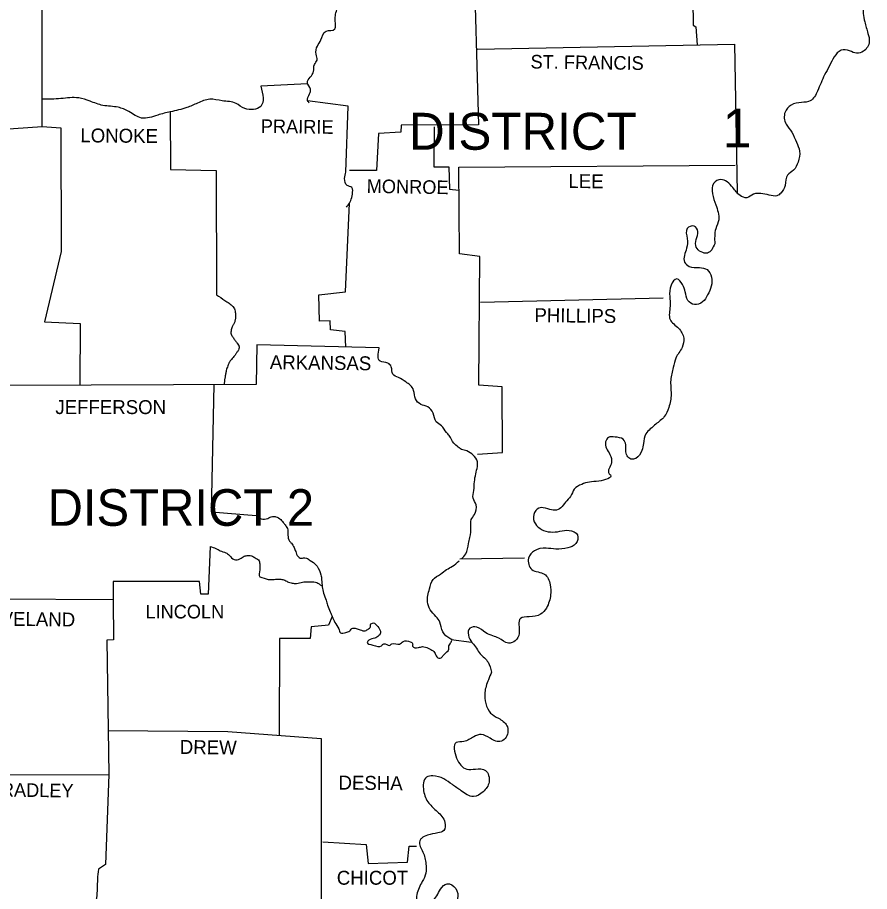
# Model space of a CAD drawing. Extents: x 1373884 to 1377798, y 1168424 to 1170626.
# Drawn here: x 1376598.2 to 1376861.3, y 1169816.4 to 1170086.2 of the extents above; entities that cross this region are included whole.
import ezdxf

# ---------------------------------------------------------------- set-up
doc = ezdxf.new("R2010")
doc.units = 0
doc.layers.add('R_Draft', color=7, linetype='Continuous')

msp = doc.modelspace()

# ---------------------------------------------------------------- linework, layer by layer
at = {"layer": 'R_Draft'}
for p, q in [((1376734.79, 1169919.1), (1376754.79, 1169919.4)), ((1376691.69, 1169911.1), (1376692.27, 1169910.78)), ((1376738.39, 1169893.3), (1376732.09, 1169894.1))]:
    msp.add_line(p, q, dxfattribs=at)
for points in [[(1376568.89, 1170039.7), (1376591.39, 1170039.8), (1376592.39, 1170051.6), (1376605.79, 1170052.6), (1376605.79, 1170106.2), (1376588.79, 1170106.7), (1376589.09, 1170159.4), (1376567.69, 1170160.8), (1376567.39, 1170184.4), (1376566.69, 1170185.6), (1376567.29, 1170200.4), (1376579.69, 1170200.8), (1376580.19, 1170213), (1376593.79, 1170213.5), (1376593.99, 1170221.4), (1376591.59, 1170224.5), (1376590.99, 1170231.2), (1376597.99, 1170232.2), (1376597.69, 1170257.1), (1376599.39, 1170257.2), (1376599.19, 1170281)], [(1376806.29, 1170122.79), (1376806.79, 1170083.9), (1376807.69, 1170083.3), (1376808.01, 1170077.77)], [(1376738.99, 1170107.9), (1376740.49, 1170053.1), (1376716.69, 1170053), (1376716.59, 1170050.8), (1376709.69, 1170050.4), (1376709.09, 1170039), (1376700.69, 1170039)], [(1376740.19, 1170076.4), (1376819.59, 1170078)], [(1376819.59, 1170078), (1376820.43, 1170032.2)], [(1376687.79, 1170065.7), (1376673.29, 1170065)], [(1376699.59, 1170038.5), (1376700.29, 1170058.9), (1376687.79, 1170060.5)], [(1376645.29, 1170057.08), (1376645.49, 1170039.3), (1376659.59, 1170039), (1376659.69, 1170000.6)], [(1376605.79, 1170052.6), (1376611.59, 1170052.2), (1376611.69, 1170014), (1376606.49, 1169992.3), (1376617.59, 1169991.8), (1376617.49, 1169972.69)], [(1376726.89, 1170052.5), (1376726.79, 1170040.1), (1376731.39, 1170040.1), (1376731.59, 1170033.2), (1376734.49, 1170032.9)], [(1376740.19, 1169951.4), (1376747.99, 1169951.9), (1376747.89, 1169972.2), (1376740.59, 1169972.7), (1376740.99, 1170012.4), (1376734.69, 1170013.3), (1376734.49, 1170040), (1376819.79, 1170040.6)], [(1376699.54, 1169984.48), (1376699.39, 1169989.3), (1376694.89, 1169989.8), (1376694.79, 1169992.6), (1376691.49, 1169992.5), (1376691.29, 1170000.6), (1376699.49, 1170001.5), (1376700.69, 1170028.9)], [(1376741.19, 1169998.3), (1376797.59, 1169999.7)], [(1376709.89, 1169984.2), (1376672.09, 1169985.2), (1376671.89, 1169972.9), (1376595.39, 1169972.6)], [(1376658.83, 1169972.85), (1376657.99, 1169933.6), (1376671.89, 1169932.5)], [(1376657.69, 1169922.9), (1376657.09, 1169908.2), (1376654.79, 1169908.2), (1376654.39, 1169912.1), (1376627.79, 1169912.1), (1376627.79, 1169906.5)], [(1376592.19, 1169906.8), (1376627.59, 1169906.6)], [(1376627.79, 1169906.6), (1376627.89, 1169894.1), (1376625.79, 1169894), (1376626.39, 1169852.5)], [(1376695.39, 1169901.3), (1376694.19, 1169898.6), (1376688.89, 1169898.1), (1376688.59, 1169894.5), (1376679.09, 1169894.5), (1376678.99, 1169864.6)], [(1376626.09, 1169866.1), (1376663.19, 1169865.8), (1376691.99, 1169863.6)], [(1376691.99, 1169863.6), (1376691.99, 1169803.8), (1376692.79, 1169746.3)], [(1376581.19, 1169852.4), (1376626.39, 1169852.5)], [(1376626.39, 1169852.5), (1376625.39, 1169824.7), (1376623.19, 1169823.3)], [(1376692.49, 1169831.7), (1376705.89, 1169830.9), (1376706.49, 1169825.1), (1376718.59, 1169825.5), (1376719.09, 1169830.4), (1376721.39, 1169830.4)]]:
    msp.add_lwpolyline(points, dxfattribs=at)
for points in [[(1376688.29, 1170059.8), (1376687.79, 1170060.5), (1376688.39, 1170062.7), (1376688.69, 1170064.1), (1376687.69, 1170066.1), (1376688.59, 1170067.8), (1376689.59, 1170069.6), (1376689.89, 1170071.7), (1376690.69, 1170073.1), (1376690.39, 1170074.9), (1376690.79, 1170077.4), (1376691.89, 1170079.3), (1376693.49, 1170082), (1376696.19, 1170082.7), (1376696.39, 1170083.8), (1376696.29, 1170086.3), (1376697.39, 1170090), (1376697.79, 1170091.3), (1376697.39, 1170092.5), (1376694.99, 1170093.9), (1376695.19, 1170096), (1376693.99, 1170098), (1376691.49, 1170098.9), (1376690.79, 1170102.3), (1376690.79, 1170105.3), (1376691.89, 1170108.2), (1376693.59, 1170110.3), (1376695.39, 1170111.1), (1376695.89, 1170113.1), (1376698.09, 1170115.3), (1376699.99, 1170116.2), (1376700.49, 1170119.5)], [(1376856.89, 1170115.5), (1376857.29, 1170112.6), (1376855.59, 1170109.5), (1376854.99, 1170106.4), (1376855.29, 1170103.3), (1376852.09, 1170101.6), (1376849.29, 1170099.6), (1376850.89, 1170097.2), (1376853.89, 1170095), (1376856.89, 1170093.3), (1376858.79, 1170091.6), (1376859.29, 1170087.5), (1376859.79, 1170084.9), (1376860.79, 1170081.3), (1376861.19, 1170078.8), (1376859.39, 1170075.8), (1376857.29, 1170075.2), (1376855.09, 1170075.9), (1376852.49, 1170076.1), (1376850.39, 1170074.1), (1376848.89, 1170071.3), (1376847.39, 1170068.5), (1376846.29, 1170066.1), (1376845.19, 1170063.5), (1376842.99, 1170060.5), (1376840.29, 1170060), (1376837.09, 1170059.2), (1376835.19, 1170057), (1376835.49, 1170053.3), (1376837.29, 1170050.8), (1376838.69, 1170047.7), (1376839.69, 1170045), (1376839.19, 1170041.6), (1376837.79, 1170039.1), (1376835.99, 1170037.6), (1376835.19, 1170034.4), (1376833.89, 1170032), (1376832.69, 1170031.2), (1376830.29, 1170031.4), (1376827.69, 1170031.9), (1376825.49, 1170031.7), (1376823.39, 1170030.6), (1376821.29, 1170031.3), (1376819.09, 1170033.7), (1376817.29, 1170035.5), (1376815.29, 1170036.2), (1376813.19, 1170035.1), (1376812.79, 1170031.8), (1376813.79, 1170028.4), (1376814.69, 1170023.8), (1376813.79, 1170021), (1376813.49, 1170016.4)], [(1376856.89, 1170115.5), (1376857.29, 1170112.6), (1376855.59, 1170109.5), (1376854.99, 1170106.4), (1376855.29, 1170103.3), (1376852.09, 1170101.6), (1376849.29, 1170099.6), (1376850.89, 1170097.2), (1376853.89, 1170095), (1376856.89, 1170093.3), (1376858.79, 1170091.6), (1376859.29, 1170087.5), (1376859.79, 1170084.9), (1376860.79, 1170081.3), (1376861.19, 1170078.8), (1376859.39, 1170075.8), (1376857.29, 1170075.2), (1376855.09, 1170075.9), (1376852.49, 1170076.1), (1376850.39, 1170074.1), (1376848.89, 1170071.3), (1376847.39, 1170068.5), (1376846.29, 1170066.1), (1376845.19, 1170063.5), (1376842.99, 1170060.5), (1376840.29, 1170060), (1376837.09, 1170059.2), (1376835.19, 1170057), (1376835.49, 1170053.3), (1376837.29, 1170050.8), (1376838.69, 1170047.7), (1376839.69, 1170045), (1376839.19, 1170041.6), (1376837.79, 1170039.1), (1376835.99, 1170037.6), (1376835.19, 1170034.4), (1376833.89, 1170032), (1376832.69, 1170031.2), (1376830.29, 1170031.4), (1376827.69, 1170031.9), (1376825.49, 1170031.7), (1376823.39, 1170030.6), (1376821.29, 1170031.3), (1376819.09, 1170033.7), (1376817.29, 1170035.5), (1376815.29, 1170036.2), (1376813.19, 1170035.1), (1376812.79, 1170031.8), (1376813.79, 1170028.4), (1376814.69, 1170023.8), (1376813.79, 1170021), (1376813.49, 1170016.4)], [(1376673.29, 1170065), (1376673.29, 1170058.8), (1376668.39, 1170058.1), (1376665.69, 1170059.7), (1376661.39, 1170060.5), (1376657.59, 1170061), (1376653.79, 1170059.8), (1376650.49, 1170058.4), (1376645.39, 1170057.1), (1376641.49, 1170056.1), (1376636.49, 1170055.2), (1376632.59, 1170057.2), (1376629.29, 1170058.5), (1376624.59, 1170059.1), (1376620.59, 1170060.4), (1376617.09, 1170061.4), (1376611.59, 1170061.2), (1376605.79, 1170060.99)], [(1376699.79, 1170027.7), (1376700.69, 1170028.9), (1376701.09, 1170029.7), (1376701.59, 1170031.7), (1376701.39, 1170033.7), (1376699.99, 1170034.4), (1376699.19, 1170036.5), (1376699.59, 1170038.5)], [(1376813.49, 1170016.4), (1376811.19, 1170013.5), (1376807.79, 1170015.3), (1376807.79, 1170017.7), (1376808.29, 1170020.2), (1376807.09, 1170021.8), (1376804.99, 1170021.1), (1376804.99, 1170018), (1376804.79, 1170015), (1376804.19, 1170010.7), (1376805.59, 1170009.4), (1376808.79, 1170009), (1376811.09, 1170008.4), (1376812.49, 1170006.1), (1376812.39, 1170003.3), (1376811.29, 1170000.6), (1376809.69, 1169998.4), (1376807.19, 1169997.6), (1376805.19, 1169998.9), (1376804.39, 1170001.5), (1376803.49, 1170003.8), (1376801.79, 1170005.5), (1376799.99, 1170003.6), (1376799.59, 1170000.1), (1376799.69, 1169997.1), (1376799.69, 1169993), (1376802.29, 1169990.3), (1376803.89, 1169987.2), (1376803.39, 1169984.4), (1376801.49, 1169981.1), (1376800.69, 1169978.2), (1376799.89, 1169974.3), (1376799.99, 1169970), (1376799.29, 1169965.8), (1376797.89, 1169963), (1376795.29, 1169960.7), (1376793.59, 1169959.2), (1376792.19, 1169957.7), (1376791.49, 1169954.7), (1376790.99, 1169952.6), (1376789.09, 1169950.1), (1376787.59, 1169949.9), (1376786.39, 1169950.9), (1376785.99, 1169952.6), (1376785.99, 1169954.3), (1376785.19, 1169956), (1376782.69, 1169956.7), (1376780.69, 1169956.6), (1376779.79, 1169955.2), (1376781.09, 1169951.3), (1376781.59, 1169948.8), (1376780.89, 1169945.4), (1376781.29, 1169945), (1376777.69, 1169943.1), (1376774.79, 1169942.8), (1376772.39, 1169942.1), (1376770.09, 1169940.6), (1376768.99, 1169938.4), (1376767.39, 1169936.6), (1376765.99, 1169934.9), (1376764.09, 1169934.1), (1376761.99, 1169934.5), (1376759.19, 1169934.8), (1376757.59, 1169932.8), (1376758.09, 1169929.9), (1376759.99, 1169928.2), (1376762.79, 1169927.4), (1376765.69, 1169927.6), (1376768.49, 1169927.9), (1376771.09, 1169926.5), (1376770.59, 1169923.8), (1376768.09, 1169922.5), (1376764.39, 1169922.1), (1376761.39, 1169922.4), (1376757.79, 1169921.6), (1376755.99, 1169919.3), (1376756.99, 1169915.8), (1376760.89, 1169914.4), (1376762.69, 1169911.1), (1376762.79, 1169908), (1376761.49, 1169903.9), (1376759.69, 1169902), (1376756.19, 1169901.2), (1376753.49, 1169900.7), (1376753.09, 1169896.1), (1376751.89, 1169893.8), (1376749.79, 1169893.1), (1376746.79, 1169894.6), (1376744.99, 1169895.3), (1376742.79, 1169896.3), (1376739.99, 1169898), (1376737.89, 1169897.7), (1376738.49, 1169893.3), (1376738.69, 1169893.1), (1376741.09, 1169889.8), (1376743.49, 1169887.2), (1376744.59, 1169884.1)], [(1376813.49, 1170016.4), (1376811.19, 1170013.5), (1376807.79, 1170015.3), (1376807.79, 1170017.7), (1376808.29, 1170020.2), (1376807.09, 1170021.8), (1376804.99, 1170021.1), (1376804.99, 1170018), (1376804.79, 1170015), (1376804.19, 1170010.7), (1376805.59, 1170009.4), (1376808.79, 1170009), (1376811.09, 1170008.4), (1376812.49, 1170006.1), (1376812.39, 1170003.3), (1376811.29, 1170000.6), (1376809.69, 1169998.4), (1376807.19, 1169997.6), (1376805.19, 1169998.9), (1376804.39, 1170001.5), (1376803.49, 1170003.8), (1376801.79, 1170005.5), (1376799.99, 1170003.6), (1376799.59, 1170000.1), (1376799.69, 1169997.1), (1376799.69, 1169993), (1376802.29, 1169990.3), (1376803.89, 1169987.2), (1376803.39, 1169984.4), (1376801.49, 1169981.1), (1376800.69, 1169978.2), (1376799.89, 1169974.3), (1376799.99, 1169970), (1376799.29, 1169965.8), (1376797.89, 1169963), (1376795.29, 1169960.7), (1376793.59, 1169959.2), (1376792.19, 1169957.7), (1376791.49, 1169954.7), (1376790.99, 1169952.6), (1376789.09, 1169950.1), (1376787.59, 1169949.9), (1376786.39, 1169950.9), (1376785.99, 1169952.6), (1376785.99, 1169954.3), (1376785.19, 1169956), (1376782.69, 1169956.7), (1376780.69, 1169956.6), (1376779.79, 1169955.2), (1376781.09, 1169951.3), (1376781.59, 1169948.8), (1376780.89, 1169945.4), (1376781.29, 1169945), (1376777.69, 1169943.1), (1376774.79, 1169942.8), (1376772.39, 1169942.1), (1376770.09, 1169940.6), (1376768.99, 1169938.4), (1376767.39, 1169936.6), (1376765.99, 1169934.9), (1376764.09, 1169934.1), (1376761.99, 1169934.5), (1376759.19, 1169934.8), (1376757.59, 1169932.8), (1376758.09, 1169929.9), (1376759.99, 1169928.2), (1376762.79, 1169927.4), (1376765.69, 1169927.6), (1376768.49, 1169927.9), (1376771.09, 1169926.5), (1376770.59, 1169923.8), (1376768.09, 1169922.5), (1376764.39, 1169922.1), (1376761.39, 1169922.4), (1376757.79, 1169921.6), (1376755.99, 1169919.3), (1376756.99, 1169915.8), (1376760.89, 1169914.4), (1376762.69, 1169911.1), (1376762.79, 1169908), (1376761.49, 1169903.9), (1376759.69, 1169902), (1376756.19, 1169901.2), (1376753.49, 1169900.7), (1376753.09, 1169896.1), (1376751.89, 1169893.8), (1376749.79, 1169893.1), (1376746.79, 1169894.6), (1376744.99, 1169895.3), (1376742.79, 1169896.3), (1376739.99, 1169898), (1376737.89, 1169897.7), (1376738.49, 1169893.3), (1376738.69, 1169893.1), (1376741.09, 1169889.8), (1376743.49, 1169887.2), (1376744.59, 1169884.1)], [(1376659.69, 1170000.6), (1376662.19, 1169998.9), (1376662.87, 1169998.46), (1376663.53, 1169998.01), (1376664.17, 1169997.52), (1376664.48, 1169997.23), (1376664.64, 1169997.07), (1376664.79, 1169996.9), (1376665.19, 1169996.28), (1376665.39, 1169995.6), (1376665.47, 1169994.9), (1376665.48, 1169994.55), (1376665.49, 1169994.2), (1376665.5, 1169993.73), (1376665.47, 1169993.25), (1376665.4, 1169992.77), (1376665.29, 1169992.3), (1376665.13, 1169991.89), (1376664.9, 1169991.49), (1376664.68, 1169991.11), (1376664.49, 1169990.7), (1376664.29, 1169990.08), (1376664.14, 1169989.43), (1376664.29, 1169988.2), (1376664.43, 1169987.97), (1376664.57, 1169987.74), (1376664.87, 1169987.29), (1376665.49, 1169986.4), (1376665.77, 1169986.03), (1376666.07, 1169985.65), (1376666.48, 1169985.09), (1376666.54, 1169985), (1376666.59, 1169984.9), (1376666.68, 1169984.26), (1376666.41, 1169983.57), (1376665.96, 1169982.87), (1376665.71, 1169982.53), (1376665.49, 1169982.2), (1376665.26, 1169981.87), (1376665.02, 1169981.56), (1376664.5, 1169980.97), (1376664.01, 1169980.37), (1376663.79, 1169980.04), (1376663.59, 1169979.7), (1376663.27, 1169979.02), (1376662.99, 1169978.33), (1376662.59, 1169976.9), (1376662.41, 1169975.89), (1376662.23, 1169974.89), (1376661.92, 1169972.86)], [(1376735.29, 1169919.1), (1376736.59, 1169920.7), (1376737.49, 1169923.8), (1376737.89, 1169925.7), (1376738.19, 1169929), (1376738.29, 1169931.2), (1376739.29, 1169932.8), (1376739.79, 1169935.8), (1376738.89, 1169937.8), (1376739.09, 1169940.2), (1376739.29, 1169942.9), (1376739.69, 1169945.3), (1376740.19, 1169947.6), (1376740.19, 1169949.1), (1376738.89, 1169951.1), (1376736.89, 1169952.4), (1376735.29, 1169952.9), (1376734.29, 1169953.6), (1376732.89, 1169954.8), (1376731.49, 1169957.2), (1376730.69, 1169958.1), (1376729.09, 1169960.2), (1376727.49, 1169961.4), (1376726.49, 1169964.1), (1376724.89, 1169966), (1376722.69, 1169966.8), (1376721.09, 1169968.5), (1376720.49, 1169971.1), (1376719.49, 1169972.7), (1376718.09, 1169973.7), (1376715.79, 1169975.1), (1376714.09, 1169976.1), (1376713.59, 1169978.4), (1376712.59, 1169979.5), (1376710.19, 1169980.1), (1376709.89, 1169984.2)], [(1376671.89, 1169932.5), (1376673.39, 1169931.5), (1376675.49, 1169931.6), (1376676.89, 1169932.2), (1376677.99, 1169932.1), (1376679.49, 1169931.2), (1376680.49, 1169930), (1376681.19, 1169929.1), (1376681.69, 1169927.7), (1376681.69, 1169926.4), (1376682.19, 1169924.6), (1376682.79, 1169923.9), (1376683.59, 1169922.6), (1376684.09, 1169921.4), (1376684.39, 1169920.6), (1376685.49, 1169919.3), (1376686.49, 1169919.4), (1376687.39, 1169919.3), (1376688.59, 1169918.6), (1376690.39, 1169917.2), (1376690.69, 1169916.8), (1376691.89, 1169914.2), (1376692.09, 1169912.6), (1376692.29, 1169910.5), (1376692.69, 1169908.5), (1376693.49, 1169906.3), (1376693.89, 1169904.8), (1376694.79, 1169902.7), (1376695.39, 1169901.3), (1376696.19, 1169899.5), (1376697.39, 1169897.5), (1376697.89, 1169896.3), (1376699.59, 1169896.4), (1376700.79, 1169896.9), (1376701.69, 1169897.7), (1376702.79, 1169897.6), (1376703.99, 1169897.2), (1376705.59, 1169896.9), (1376706.59, 1169897.5), (1376707.09, 1169897.9), (1376707.19, 1169898.8), (1376708.09, 1169899.3), (1376709.09, 1169898.6), (1376710.19, 1169897), (1376710.19, 1169896), (1376709.79, 1169895.4), (1376708.49, 1169894.6), (1376706.69, 1169894), (1376706.19, 1169893.3), (1376707.89, 1169892.5), (1376710.59, 1169892.3), (1376711.29, 1169892.9), (1376713.09, 1169892.4), (1376713.79, 1169892.9), (1376716.19, 1169892.8), (1376717.29, 1169893.6), (1376719.49, 1169893.5), (1376720.19, 1169893), (1376720.19, 1169892.1), (1376721.99, 1169891.7), (1376723.29, 1169892), (1376724.99, 1169891.5), (1376726.49, 1169890.7), (1376727.29, 1169889.6), (1376728.29, 1169888.4), (1376729.19, 1169888.7), (1376729.89, 1169889.6), (1376731.39, 1169891.2), (1376731.39, 1169892.2), (1376731.79, 1169892.9), (1376732.29, 1169893.9)], [(1376657.69, 1169922.9), (1376659.49, 1169922.3), (1376660.79, 1169921.6), (1376662.49, 1169921), (1376663.59, 1169920.2), (1376665.09, 1169918.9), (1376666.89, 1169919.1), (1376668.19, 1169919.9), (1376669.49, 1169920.1), (1376670.49, 1169920), (1376671.59, 1169919.4), (1376672.79, 1169918.5), (1376672.99, 1169917.2), (1376672.99, 1169915.7), (1376672.99, 1169913.6), (1376673.69, 1169913.3), (1376676.19, 1169912.7), (1376677.89, 1169912.8), (1376679.49, 1169912.8), (1376680.79, 1169912.5), (1376681.89, 1169911.9), (1376682.69, 1169911.7), (1376683.89, 1169911.5), (1376684.89, 1169911.6), (1376686.59, 1169912), (1376687.59, 1169912), (1376689.19, 1169912), (1376690.19, 1169911.9), (1376691.69, 1169911.1)], [(1376732.39, 1169894.2), (1376731.69, 1169894.5), (1376729.49, 1169896.6), (1376728.59, 1169899.6), (1376727.39, 1169901.3), (1376725.59, 1169903.4), (1376724.79, 1169905.8), (1376725.39, 1169909.8), (1376726.49, 1169912.7), (1376728.79, 1169914.4), (1376730.69, 1169915.8), (1376732.49, 1169916.8), (1376734.59, 1169918.5)], [(1376744.59, 1169884.1), (1376743.59, 1169881.8), (1376742.49, 1169877.8), (1376742.79, 1169874.4), (1376744.29, 1169871.5), (1376746.69, 1169869.9), (1376749.29, 1169867.6), (1376749.09, 1169864.1), (1376747.59, 1169862.8), (1376744.09, 1169863.7), (1376741.39, 1169864.9), (1376739.09, 1169864.2), (1376735.99, 1169862.7), (1376733.69, 1169862.4), (1376733.79, 1169857.6), (1376736.89, 1169854.2), (1376739.59, 1169854.2), (1376742.69, 1169853.8), (1376743.79, 1169850.2), (1376741.99, 1169847.2), (1376738.99, 1169845.7), (1376735.19, 1169847.5), (1376732.49, 1169849.4), (1376729.79, 1169851.2), (1376726.39, 1169852.1), (1376724.49, 1169851.7), (1376723.59, 1169847.5), (1376725.19, 1169843.7), (1376727.79, 1169841.1), (1376730.19, 1169837.7), (1376729.79, 1169835.2), (1376727.99, 1169834.5), (1376724.79, 1169833.8), (1376722.89, 1169832.8), (1376722.39, 1169832), (1376723.39, 1169828.6), (1376724.29, 1169824.9), (1376724.29, 1169822.1), (1376723.19, 1169819.5), (1376721.49, 1169815.5), (1376721.69, 1169812.9), (1376722.89, 1169811.7), (1376724.39, 1169812.1), (1376726.39, 1169813.5), (1376727.69, 1169815.1), (1376728.79, 1169817.1), (1376730.89, 1169818.8), (1376733.49, 1169817.3), (1376734.09, 1169814.2), (1376732.59, 1169811.5), (1376730.49, 1169810.3), (1376727.89, 1169809.3), (1376725.99, 1169807.1), (1376726.49, 1169804.5), (1376727.99, 1169803.1), (1376731.69, 1169803.8), (1376734.19, 1169804.9), (1376735.59, 1169806.3), (1376737.29, 1169808), (1376738.19, 1169809.7), (1376739.49, 1169811.5), (1376741.79, 1169812), (1376742.89, 1169810.5), (1376742.49, 1169807.1), (1376741.09, 1169803.9), (1376739.19, 1169801.2), (1376737.09, 1169799.3), (1376734.49, 1169795.2), (1376734.99, 1169791.4), (1376735.99, 1169788.3), (1376737.39, 1169785.9), (1376739.79, 1169786.4), (1376742.49, 1169786.7), (1376744.09, 1169785.4), (1376743.89, 1169782.6), (1376741.89, 1169779.9), (1376739.99, 1169777.3), (1376738.99, 1169773.7), (1376739.39, 1169771.2), (1376739.39, 1169768.9), (1376738.59, 1169766.4), (1376737.19, 1169765), (1376733.49, 1169765.1), (1376729.59, 1169765.5), (1376727.49, 1169764.3), (1376727.89, 1169760.9), (1376730.19, 1169758.4), (1376731.79, 1169757.1), (1376734.09, 1169754.3), (1376735.09, 1169752), (1376734.79, 1169750), (1376733.39, 1169748.3), (1376729.29, 1169746.3)], [(1376744.59, 1169884.1), (1376743.59, 1169881.8), (1376742.49, 1169877.8), (1376742.79, 1169874.4), (1376744.29, 1169871.5), (1376746.69, 1169869.9), (1376749.29, 1169867.6), (1376749.09, 1169864.1), (1376747.59, 1169862.8), (1376744.09, 1169863.7), (1376741.39, 1169864.9), (1376739.09, 1169864.2), (1376735.99, 1169862.7), (1376733.69, 1169862.4), (1376733.79, 1169857.6), (1376736.89, 1169854.2), (1376739.59, 1169854.2), (1376742.69, 1169853.8), (1376743.79, 1169850.2), (1376741.99, 1169847.2), (1376738.99, 1169845.7), (1376735.19, 1169847.5), (1376732.49, 1169849.4), (1376729.79, 1169851.2), (1376726.39, 1169852.1), (1376724.49, 1169851.7), (1376723.59, 1169847.5), (1376725.19, 1169843.7), (1376727.79, 1169841.1), (1376730.19, 1169837.7), (1376729.79, 1169835.2), (1376727.99, 1169834.5), (1376724.79, 1169833.8), (1376722.89, 1169832.8), (1376722.39, 1169832), (1376723.39, 1169828.6), (1376724.29, 1169824.9), (1376724.29, 1169822.1), (1376723.19, 1169819.5), (1376721.49, 1169815.5), (1376721.69, 1169812.9), (1376722.89, 1169811.7), (1376724.39, 1169812.1), (1376726.39, 1169813.5), (1376727.69, 1169815.1), (1376728.79, 1169817.1), (1376730.89, 1169818.8), (1376733.49, 1169817.3), (1376734.09, 1169814.2), (1376732.59, 1169811.5), (1376730.49, 1169810.3), (1376727.89, 1169809.3), (1376725.99, 1169807.1), (1376726.49, 1169804.5), (1376727.99, 1169803.1), (1376731.69, 1169803.8), (1376734.19, 1169804.9), (1376735.59, 1169806.3), (1376737.29, 1169808), (1376738.19, 1169809.7), (1376739.49, 1169811.5), (1376741.79, 1169812), (1376742.89, 1169810.5), (1376742.49, 1169807.1), (1376741.09, 1169803.9), (1376739.19, 1169801.2), (1376737.09, 1169799.3), (1376734.49, 1169795.2), (1376734.99, 1169791.4), (1376735.99, 1169788.3), (1376737.39, 1169785.9), (1376739.79, 1169786.4), (1376742.49, 1169786.7), (1376744.09, 1169785.4), (1376743.89, 1169782.6), (1376741.89, 1169779.9), (1376739.99, 1169777.3), (1376738.99, 1169773.7), (1376739.39, 1169771.2), (1376739.39, 1169768.9), (1376738.59, 1169766.4), (1376737.19, 1169765), (1376733.49, 1169765.1), (1376729.59, 1169765.5), (1376727.49, 1169764.3), (1376727.89, 1169760.9), (1376730.19, 1169758.4), (1376731.79, 1169757.1), (1376734.09, 1169754.3), (1376735.09, 1169752), (1376734.79, 1169750), (1376733.39, 1169748.3), (1376729.29, 1169746.3)], [(1376623.19, 1169823.3), (1376622.89, 1169820.2), (1376622.79, 1169817.3), (1376622.59, 1169814.5), (1376622.59, 1169812.4), (1376623.79, 1169810.1), (1376624.49, 1169807.9), (1376625.19, 1169806), (1376626.59, 1169803.5), (1376627.89, 1169801.6), (1376628.29, 1169798.9), (1376627.49, 1169797.5), (1376625.99, 1169795.4), (1376625.89, 1169791.6), (1376624.09, 1169790.4), (1376621.79, 1169788.4), (1376620.49, 1169787.5), (1376619.09, 1169786.6), (1376617.59, 1169785), (1376615.39, 1169783.5), (1376613.79, 1169781), (1376611.99, 1169779.1), (1376610.49, 1169778.1), (1376608.39, 1169776.8), (1376607.49, 1169774.8), (1376606.79, 1169771.1), (1376607.09, 1169768.4), (1376607.49, 1169766), (1376606.99, 1169763), (1376607.49, 1169759.7), (1376607.99, 1169757.1), (1376608.79, 1169754.8), (1376609.89, 1169752.2), (1376611.29, 1169749.8), (1376614.29, 1169746.1)]]:
    msp.add_spline(points, degree=3, dxfattribs=at)

# ---------------------------------------------------------------- texts
for s, height, rotation, p in [('ST. FRANCIS', 4.1994, 359.2216, (1376756.59, 1170070.5)), ('PRAIRIE', 4.201, 359.2116, (1376673.29, 1170050.6)), ('LONOKE', 4.301, 359.4974, (1376617.59, 1170047.7)), ('MONROE', 4.199, 359.0331, (1376705.99, 1170032.1)), ('LEE', 4.301, 359.4327, (1376768.29, 1170033.6)), ('PHILLIPS', 4.3, 359.3179, (1376757.79, 1169992.2)), ('ARKANSAS', 4.3, 359.2678, (1376676.09, 1169977.7)), ('CLEVELAND', 4.301, 359.3376, (1376581.79, 1169898.6)), ('DREW', 4.3, 359.2258, (1376648.29, 1169858.9)), ('BRADLEY', 4.199, 359.1449, (1376589.29, 1169845.8)), ('DESHA', 4.3, 359.3704, (1376697.29, 1169847.9))]:
    msp.add_text(s, height=height, rotation=rotation, dxfattribs=at).set_placement(p)
for s, height, p in [('1', 12, (1376815.89, 1170046.1)), ('DISTRICT', 11.4, (1376719.09, 1170045.4)), ('JEFFERSON', 4.3, (1376609.89, 1169963.8)), ('DISTRICT 2', 11.3, (1376607.49, 1169929.3)), ('LINCOLN', 4.2, (1376637.69, 1169900.7)), ('CHICOT', 4.3, (1376696.79, 1169818.5))]:
    msp.add_text(s, height=height, dxfattribs=at).set_placement(p)

doc.saveas('drawing.dxf')
